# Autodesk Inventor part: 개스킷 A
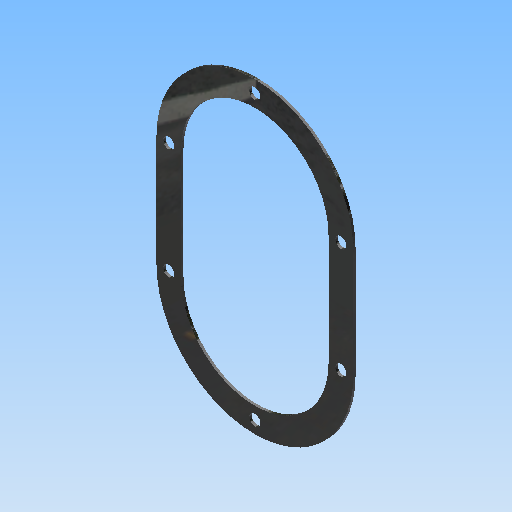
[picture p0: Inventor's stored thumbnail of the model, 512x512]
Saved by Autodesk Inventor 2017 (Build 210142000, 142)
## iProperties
Created: 2020-04
Part Number: 개스킷 A
Material: 고무
Document SubType Name: Modeling
Designer: mduedu
Density: 0.93 g/cm^3
Mass: 2.61813 g
Surface Area: 62.9733 cm^2
Volume: 2.81519 cm^3
Appearance: 고무 - 검은색 - 버전 1.1
Author: mduedu
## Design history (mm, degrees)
sketch "스케치1"
  geometry: L1 (-40, 0)-(-40, -45); L2 (40, 0)-(40, -45); A1 r 40 centre (0, 0) between (40, 0) and (-40, 0); A2 r 40 centre (0, -45) between (-40, -45) and (40, -45); 1 further point
  constraints: 4 end point, 4 point on circle, 4 tangent, 2 centre point, 1 coincident, 1 equal radius, 1 vertical alignment
  dimensions: "d0" = 80 diameter of A1; "d21" = 45 distance of point (0, 0) A2.centre
extrude "돌출1" new body sketch "스케치1" distance "d1" = 1; taper "d2" = 0 deg
sketch "스케치4"
  geometry: L1 (-30, 0)-(-30, -45); L2 (30, 0)-(30, -45); A1 r 30 centre (0, 0) between (30, 0) and (-30, 0); A2 r 30 centre (0, -45) between (-30, -45) and (30, -45); 1 further point
  constraints: 4 end point, 4 point on circle, 4 tangent, 2 centre point, 1 coincident, 1 equal radius, 1 vertical alignment
  dimensions: "d17" = 60 diameter of A1; "d24" = 45 distance of point (0, 0) A2.centre
extrude "돌출3" cut sketch "스케치4" stored distance "d18" = 1; taper "d19" = 0 deg
sketch "스케치3"
  geometry: A1 r 35 centre (0, 0) between (0, 35) and (-35, 0); A2 r 35 centre (0, -45) between (-35, -45) and (0, -80); 3 further points
  constraints: 6 point on circle, 5 vertical alignment, 3 horizontal alignment, 2 centre point, 1 coincident, 1 equal radius
  dimensions: "d6" = 70 diameter of A1; "d28" = 45 distance of point (0, 0) A2.centre
hole "구멍1" sketch "스케치3" at (0, 35), (-35, 0), (35, 0), (35, -45), (-35, -45), (0, -80) diameter "d7" = 4.5; stored, may be unused: countersink angle "d11" = 90 deg, drill point angle "d13" = 118 deg; dims "d8" = 6, "d9" = 4, "d10" = 2, "d12" = 8
node "솔리드1"
